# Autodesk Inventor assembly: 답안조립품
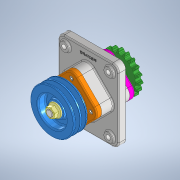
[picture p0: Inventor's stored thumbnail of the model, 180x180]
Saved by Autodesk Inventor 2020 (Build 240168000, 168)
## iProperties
Created: 2021-07
Part Number: 답안조립품
Document SubType Name: Assembly
Designer: Owner
Author: Owner
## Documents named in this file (16)
- C:\Users\Owner\Desktop\710707V1011\답안조립품.iam
- C:\Users\Owner\Desktop\710707V1011\본체.ipt
- C:\Users\Owner\Desktop\710707V1011\M16 너트.ipt
- C:\Users\Owner\Desktop\710707V1011\V-벨트풀리.ipt
- C:\Users\Owner\Desktop\710707V1011\멈춤나사 M4.ipt
- C:\Users\Owner\Desktop\710707V1011\베어링 6206.ipt
- C:\Users\Owner\Desktop\710707V1011\볼트 M6.ipt
- C:\Users\Owner\Desktop\710707V1011\부시.ipt
- C:\Users\Owner\Desktop\710707V1011\오일실 30x42x8.ipt
- C:\Users\Owner\Desktop\710707V1011\오일실 30x45x8.ipt
- C:\Users\Owner\Desktop\710707V1011\체인 스프로킷.ipt
- C:\Users\Owner\Desktop\710707V1011\축.ipt
- C:\Users\Owner\Desktop\710707V1011\커버A.ipt
- C:\Users\Owner\Desktop\710707V1011\커버B.ipt
- C:\Users\Owner\Desktop\710707V1011\키 6x6x18.ipt
- C:\Users\Owner\Desktop\710707V1011\키 6x6x20.ipt
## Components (3 placed, 2 different names)
1. M16 너트:1 — 각도:3
2. V-벨트풀리:1 — 각도:1
3. M16 너트:2
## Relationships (2: Angle 2)
- 각도:1 [Angle]: V-벨트풀리:1
- 각도:3 [Angle]: M16 너트:1
